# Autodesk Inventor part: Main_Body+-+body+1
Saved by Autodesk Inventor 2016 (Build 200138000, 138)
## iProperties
Created: 2016-03
Part Number: Main_Body+-+body+1
Material: Generic
Document SubType Name: Modeling
Designer: fisher
Density: 1 g/cm^3
Appearance: Default
Title: /vol/tmp/translate-7265505631474094218/56e724fce4b014264326d133.step
Revision Number: NONE
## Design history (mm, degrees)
feature "body 1"
body "Solid1"
